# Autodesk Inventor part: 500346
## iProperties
Created: 2007-11
Part Number: 500346
Document SubType Name: Modeling
Designer: TH
Density: 7.85 g/cm^3
Mass: 28.3508 g
Surface Area: 30.7052 cm^2
Volume: 3.61157 cm^3
Material: Steel
Description: SIDE LINK BAR
Component Category: Side Component
Author: TH
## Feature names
1. Sweep1
2. Sweep2
3. Sweep3
4. Sweep4
5. Sweep5
